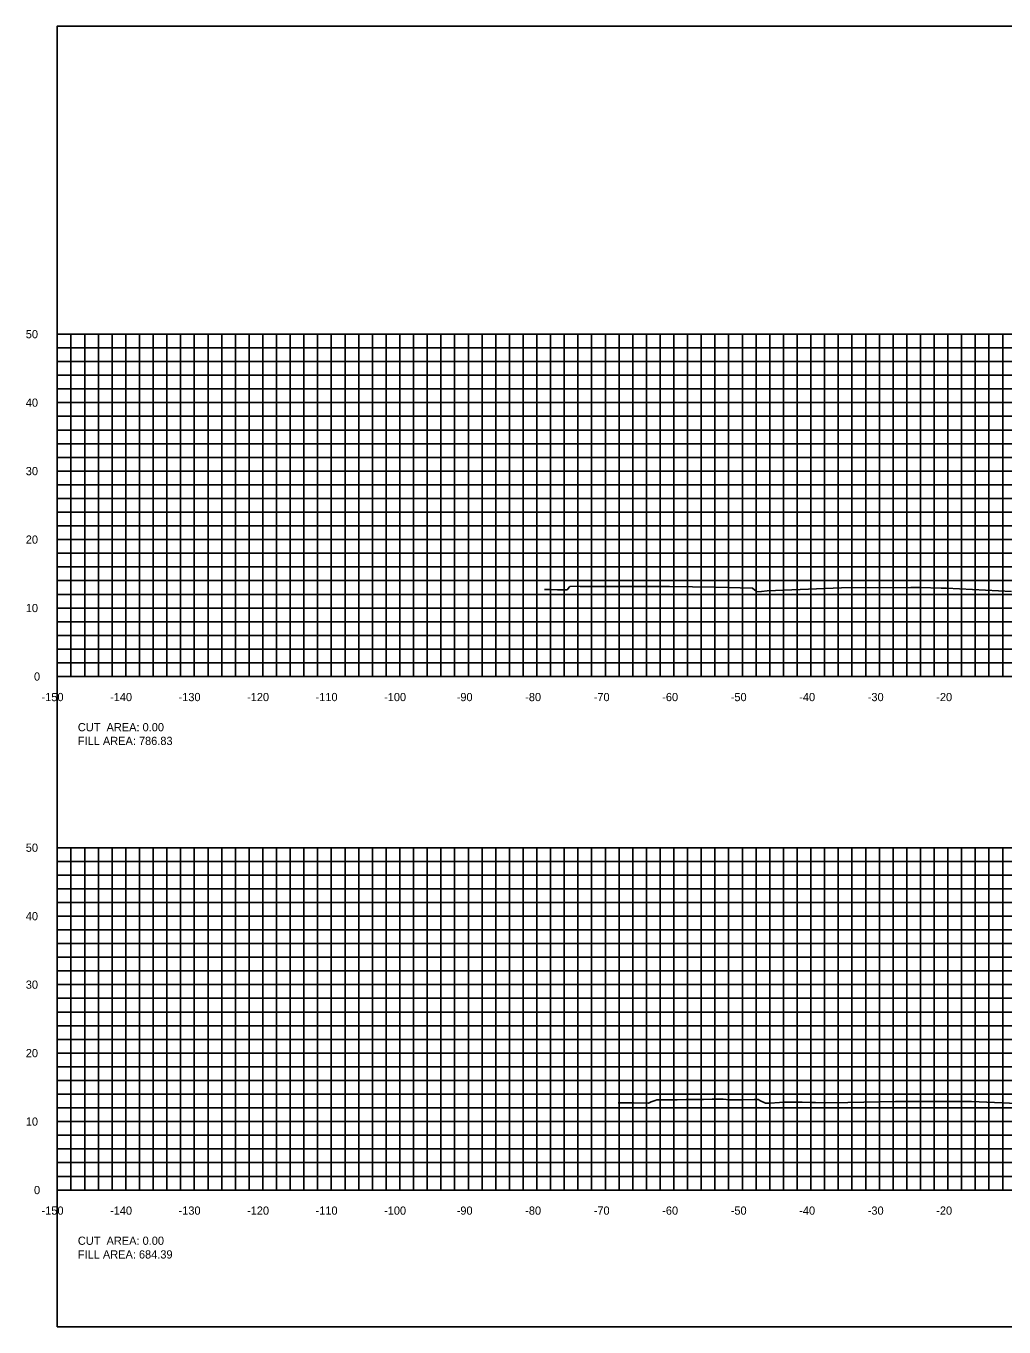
# Model space of a CAD drawing. Extents: x 1797714 to 1804825, y 249015 to 250269.
# Drawn here: x 1803496.4 to 1803639.2, y 250079.4 to 250269.4 of the extents above; entities that cross this region are included whole.
import ezdxf

# ---------------------------------------------------------------- set-up
doc = ezdxf.new("R2010")
doc.units = 0
for name, color, linetype in [('10', 7, 'Continuous'), ('31', 7, 'Continuous'), ('60', 7, 'Continuous'), ('ANNO-TXT', 7, 'Continuous'), ('Level 62', 7, 'Continuous'), ('M-ROADS', 7, 'Continuous')]:
    doc.layers.add(name, color=color, linetype=linetype)

msp = doc.modelspace()

# ---------------------------------------------------------------- linework, layer by layer
msp.add_lwpolyline([(1803501, 250079.43), (1803801, 250079.43), (1803801, 250269.43), (1803501, 250269.43)], close=True)
at = {"layer": '60'}
for p, q in [((1803500.94, 250224.43), (1803501, 250224.43)), ((1803501, 250174.43), (1803501, 250224.43)), ((1803500.94, 250214.43), (1803501, 250214.43)), ((1803500.94, 250204.43), (1803501, 250204.43)), ((1803500.94, 250194.43), (1803501, 250194.43)), ((1803500.94, 250184.43), (1803501, 250184.43)), ((1803500.94, 250174.43), (1803501, 250174.43)), ((1803501, 250174.43), (1803801, 250174.43)), ((1803501, 250174.37), (1803501, 250174.43)), ((1803511, 250174.37), (1803511, 250174.43)), ((1803521, 250174.37), (1803521, 250174.43)), ((1803531, 250174.37), (1803531, 250174.43)), ((1803541, 250174.37), (1803541, 250174.43)), ((1803551, 250174.37), (1803551, 250174.43)), ((1803561, 250174.37), (1803561, 250174.43)), ((1803571, 250174.37), (1803571, 250174.43)), ((1803581, 250174.37), (1803581, 250174.43)), ((1803591, 250174.37), (1803591, 250174.43)), ((1803601, 250174.37), (1803601, 250174.43)), ((1803611, 250174.37), (1803611, 250174.43)), ((1803621, 250174.37), (1803621, 250174.43)), ((1803631, 250174.37), (1803631, 250174.43)), ((1803500.94, 250149.43), (1803501, 250149.43)), ((1803501, 250099.43), (1803501, 250149.43)), ((1803500.94, 250139.43), (1803501, 250139.43)), ((1803500.94, 250129.43), (1803501, 250129.43)), ((1803500.94, 250119.43), (1803501, 250119.43)), ((1803500.94, 250109.43), (1803501, 250109.43)), ((1803500.94, 250099.43), (1803501, 250099.43)), ((1803501, 250099.43), (1803801, 250099.43)), ((1803501, 250099.37), (1803501, 250099.43)), ((1803511, 250099.37), (1803511, 250099.43)), ((1803521, 250099.37), (1803521, 250099.43)), ((1803531, 250099.37), (1803531, 250099.43)), ((1803541, 250099.37), (1803541, 250099.43)), ((1803551, 250099.37), (1803551, 250099.43)), ((1803561, 250099.37), (1803561, 250099.43)), ((1803571, 250099.37), (1803571, 250099.43)), ((1803581, 250099.37), (1803581, 250099.43)), ((1803591, 250099.37), (1803591, 250099.43)), ((1803601, 250099.37), (1803601, 250099.43)), ((1803611, 250099.37), (1803611, 250099.43)), ((1803621, 250099.37), (1803621, 250099.43)), ((1803631, 250099.37), (1803631, 250099.43))]:
    msp.add_line(p, q, dxfattribs=at)
at = {"layer": 'Level 62'}
for p, q in [((1803501, 250224.43), (1803801, 250224.43)), ((1803501, 250174.43), (1803501, 250224.43)), ((1803503, 250174.43), (1803503, 250224.43)), ((1803505, 250174.43), (1803505, 250224.43)), ((1803507, 250174.43), (1803507, 250224.43)), ((1803509, 250174.43), (1803509, 250224.43)), ((1803511, 250174.43), (1803511, 250224.43)), ((1803513, 250174.43), (1803513, 250224.43)), ((1803515, 250174.43), (1803515, 250224.43)), ((1803517, 250174.43), (1803517, 250224.43)), ((1803519, 250174.43), (1803519, 250224.43)), ((1803521, 250174.43), (1803521, 250224.43)), ((1803523, 250174.43), (1803523, 250224.43)), ((1803525, 250174.43), (1803525, 250224.43)), ((1803527, 250174.43), (1803527, 250224.43)), ((1803529, 250174.43), (1803529, 250224.43)), ((1803531, 250174.43), (1803531, 250224.43)), ((1803533, 250174.43), (1803533, 250224.43)), ((1803535, 250174.43), (1803535, 250224.43)), ((1803537, 250174.43), (1803537, 250224.43)), ((1803539, 250174.43), (1803539, 250224.43)), ((1803541, 250174.43), (1803541, 250224.43)), ((1803543, 250174.43), (1803543, 250224.43)), ((1803545, 250174.43), (1803545, 250224.43)), ((1803547, 250174.43), (1803547, 250224.43)), ((1803549, 250174.43), (1803549, 250224.43)), ((1803551, 250174.43), (1803551, 250224.43)), ((1803553, 250174.43), (1803553, 250224.43)), ((1803555, 250174.43), (1803555, 250224.43)), ((1803557, 250174.43), (1803557, 250224.43)), ((1803559, 250174.43), (1803559, 250224.43)), ((1803561, 250174.43), (1803561, 250224.43)), ((1803563, 250174.43), (1803563, 250224.43)), ((1803565, 250174.43), (1803565, 250224.43)), ((1803567, 250174.43), (1803567, 250224.43)), ((1803569, 250174.43), (1803569, 250224.43)), ((1803571, 250174.43), (1803571, 250224.43)), ((1803573, 250174.43), (1803573, 250224.43)), ((1803575, 250174.43), (1803575, 250224.43)), ((1803577, 250174.43), (1803577, 250224.43)), ((1803579, 250174.43), (1803579, 250224.43)), ((1803581, 250174.43), (1803581, 250224.43)), ((1803583, 250174.43), (1803583, 250224.43)), ((1803585, 250174.43), (1803585, 250224.43)), ((1803587, 250174.43), (1803587, 250224.43)), ((1803589, 250174.43), (1803589, 250224.43)), ((1803591, 250174.43), (1803591, 250224.43)), ((1803593, 250174.43), (1803593, 250224.43)), ((1803595, 250174.43), (1803595, 250224.43)), ((1803597, 250174.43), (1803597, 250224.43)), ((1803599, 250174.43), (1803599, 250224.43)), ((1803601, 250174.43), (1803601, 250224.43)), ((1803603, 250174.43), (1803603, 250224.43)), ((1803605, 250174.43), (1803605, 250224.43)), ((1803607, 250174.43), (1803607, 250224.43)), ((1803609, 250174.43), (1803609, 250224.43)), ((1803611, 250174.43), (1803611, 250224.43)), ((1803613, 250174.43), (1803613, 250224.43)), ((1803615, 250174.43), (1803615, 250224.43)), ((1803617, 250174.43), (1803617, 250224.43)), ((1803619, 250174.43), (1803619, 250224.43)), ((1803621, 250174.43), (1803621, 250224.43)), ((1803623, 250174.43), (1803623, 250224.43)), ((1803625, 250174.43), (1803625, 250224.43)), ((1803627, 250174.43), (1803627, 250224.43)), ((1803629, 250174.43), (1803629, 250224.43)), ((1803631, 250174.43), (1803631, 250224.43)), ((1803633, 250174.43), (1803633, 250224.43)), ((1803635, 250174.43), (1803635, 250224.43)), ((1803637, 250174.43), (1803637, 250224.43)), ((1803639, 250174.43), (1803639, 250224.43)), ((1803501, 250222.43), (1803801, 250222.43)), ((1803501, 250220.43), (1803801, 250220.43)), ((1803501, 250218.43), (1803801, 250218.43)), ((1803501, 250216.43), (1803801, 250216.43)), ((1803501, 250214.43), (1803801, 250214.43)), ((1803501, 250212.43), (1803801, 250212.43)), ((1803501, 250210.43), (1803801, 250210.43)), ((1803501, 250208.43), (1803801, 250208.43)), ((1803501, 250206.43), (1803801, 250206.43)), ((1803501, 250204.43), (1803801, 250204.43)), ((1803501, 250202.43), (1803801, 250202.43)), ((1803501, 250200.43), (1803801, 250200.43)), ((1803501, 250198.43), (1803801, 250198.43)), ((1803501, 250196.43), (1803801, 250196.43)), ((1803501, 250194.43), (1803801, 250194.43)), ((1803501, 250192.43), (1803801, 250192.43)), ((1803501, 250190.43), (1803801, 250190.43)), ((1803501, 250188.43), (1803801, 250188.43)), ((1803501, 250186.43), (1803801, 250186.43)), ((1803501, 250184.43), (1803801, 250184.43)), ((1803501, 250182.43), (1803801, 250182.43)), ((1803501, 250180.43), (1803801, 250180.43)), ((1803501, 250178.43), (1803801, 250178.43)), ((1803501, 250176.43), (1803801, 250176.43)), ((1803501, 250174.43), (1803801, 250174.43)), ((1803501, 250149.43), (1803801, 250149.43)), ((1803501, 250099.43), (1803501, 250149.43)), ((1803503, 250099.43), (1803503, 250149.43)), ((1803505, 250099.43), (1803505, 250149.43)), ((1803507, 250099.43), (1803507, 250149.43)), ((1803509, 250099.43), (1803509, 250149.43)), ((1803511, 250099.43), (1803511, 250149.43)), ((1803513, 250099.43), (1803513, 250149.43)), ((1803515, 250099.43), (1803515, 250149.43)), ((1803517, 250099.43), (1803517, 250149.43)), ((1803519, 250099.43), (1803519, 250149.43)), ((1803521, 250099.43), (1803521, 250149.43)), ((1803523, 250099.43), (1803523, 250149.43)), ((1803525, 250099.43), (1803525, 250149.43)), ((1803527, 250099.43), (1803527, 250149.43)), ((1803529, 250099.43), (1803529, 250149.43)), ((1803531, 250099.43), (1803531, 250149.43)), ((1803533, 250099.43), (1803533, 250149.43)), ((1803535, 250099.43), (1803535, 250149.43)), ((1803537, 250099.43), (1803537, 250149.43)), ((1803539, 250099.43), (1803539, 250149.43)), ((1803541, 250099.43), (1803541, 250149.43)), ((1803543, 250099.43), (1803543, 250149.43)), ((1803545, 250099.43), (1803545, 250149.43)), ((1803547, 250099.43), (1803547, 250149.43)), ((1803549, 250099.43), (1803549, 250149.43)), ((1803551, 250099.43), (1803551, 250149.43)), ((1803553, 250099.43), (1803553, 250149.43)), ((1803555, 250099.43), (1803555, 250149.43)), ((1803557, 250099.43), (1803557, 250149.43)), ((1803559, 250099.43), (1803559, 250149.43)), ((1803561, 250099.43), (1803561, 250149.43)), ((1803563, 250099.43), (1803563, 250149.43)), ((1803565, 250099.43), (1803565, 250149.43)), ((1803567, 250099.43), (1803567, 250149.43)), ((1803569, 250099.43), (1803569, 250149.43)), ((1803571, 250099.43), (1803571, 250149.43)), ((1803573, 250099.43), (1803573, 250149.43)), ((1803575, 250099.43), (1803575, 250149.43)), ((1803577, 250099.43), (1803577, 250149.43)), ((1803579, 250099.43), (1803579, 250149.43)), ((1803581, 250099.43), (1803581, 250149.43)), ((1803583, 250099.43), (1803583, 250149.43)), ((1803585, 250099.43), (1803585, 250149.43)), ((1803587, 250099.43), (1803587, 250149.43)), ((1803589, 250099.43), (1803589, 250149.43)), ((1803591, 250099.43), (1803591, 250149.43)), ((1803593, 250099.43), (1803593, 250149.43)), ((1803595, 250099.43), (1803595, 250149.43)), ((1803597, 250099.43), (1803597, 250149.43)), ((1803599, 250099.43), (1803599, 250149.43)), ((1803601, 250099.43), (1803601, 250149.43)), ((1803603, 250099.43), (1803603, 250149.43)), ((1803605, 250099.43), (1803605, 250149.43)), ((1803607, 250099.43), (1803607, 250149.43)), ((1803609, 250099.43), (1803609, 250149.43)), ((1803611, 250099.43), (1803611, 250149.43)), ((1803613, 250099.43), (1803613, 250149.43)), ((1803615, 250099.43), (1803615, 250149.43)), ((1803617, 250099.43), (1803617, 250149.43)), ((1803619, 250099.43), (1803619, 250149.43)), ((1803621, 250099.43), (1803621, 250149.43)), ((1803623, 250099.43), (1803623, 250149.43)), ((1803625, 250099.43), (1803625, 250149.43)), ((1803627, 250099.43), (1803627, 250149.43)), ((1803629, 250099.43), (1803629, 250149.43)), ((1803631, 250099.43), (1803631, 250149.43)), ((1803633, 250099.43), (1803633, 250149.43)), ((1803635, 250099.43), (1803635, 250149.43)), ((1803637, 250099.43), (1803637, 250149.43)), ((1803639, 250099.43), (1803639, 250149.43)), ((1803501, 250147.43), (1803801, 250147.43)), ((1803501, 250145.43), (1803801, 250145.43)), ((1803501, 250143.43), (1803801, 250143.43)), ((1803501, 250141.43), (1803801, 250141.43)), ((1803501, 250139.43), (1803801, 250139.43)), ((1803501, 250137.43), (1803801, 250137.43)), ((1803501, 250135.43), (1803801, 250135.43)), ((1803501, 250133.43), (1803801, 250133.43)), ((1803501, 250131.43), (1803801, 250131.43)), ((1803501, 250129.43), (1803801, 250129.43)), ((1803501, 250127.43), (1803801, 250127.43)), ((1803501, 250125.43), (1803801, 250125.43)), ((1803501, 250123.43), (1803801, 250123.43)), ((1803501, 250121.43), (1803801, 250121.43)), ((1803501, 250119.43), (1803801, 250119.43)), ((1803501, 250117.43), (1803801, 250117.43)), ((1803501, 250115.43), (1803801, 250115.43)), ((1803501, 250113.43), (1803801, 250113.43)), ((1803501, 250111.43), (1803801, 250111.43)), ((1803501, 250109.43), (1803801, 250109.43)), ((1803501, 250107.43), (1803801, 250107.43)), ((1803501, 250105.43), (1803801, 250105.43)), ((1803501, 250103.43), (1803801, 250103.43)), ((1803501, 250101.43), (1803801, 250101.43)), ((1803501, 250099.43), (1803801, 250099.43))]:
    msp.add_line(p, q, dxfattribs=at)
at = {"layer": 'M-ROADS'}
for points in [[(1803572.1, 250187.15), (1803572.86, 250187.13), (1803574, 250187.1), (1803574.17, 250187.09), (1803575.41, 250187.08), (1803575.78, 250187.54), (1803575.82, 250187.59), (1803577.04, 250187.61), (1803577.31, 250187.58), (1803590.38, 250187.56), (1803597.09, 250187.47), (1803602.49, 250187.31), (1803602.81, 250187.05), (1803603.05, 250186.81), (1803603.8, 250186.87), (1803604.64, 250186.92), (1803613.06, 250187.26), (1803615.47, 250187.36), (1803625.61, 250187.43), (1803626.96, 250187.44), (1803630.01, 250187.33), (1803630.15, 250187.32), (1803630.81, 250187.31), (1803640.28, 250186.86)], [(1803582.87, 250112.17), (1803582.96, 250112.18), (1803583.12, 250112.19), (1803583.61, 250112.19), (1803584.35, 250112.19), (1803584.84, 250112.19), (1803585.03, 250112.19), (1803585.14, 250112.18), (1803587.28, 250112.1), (1803587.41, 250112.16), (1803587.68, 250112.29), (1803588.25, 250112.5), (1803588.52, 250112.6), (1803591.46, 250112.63), (1803592.81, 250112.64), (1803594.46, 250112.64), (1803595.34, 250112.67), (1803596.57, 250112.68), (1803597.19, 250112.69), (1803598.21, 250112.68), (1803599.11, 250112.62), (1803600.24, 250112.63), (1803601.03, 250112.63), (1803602.73, 250112.64), (1803603.31, 250112.64), (1803603.63, 250112.48), (1803604.4, 250112.1), (1803604.68, 250112.11), (1803605.03, 250112.13), (1803606.43, 250112.23), (1803607.07, 250112.28), (1803608.7, 250112.27), (1803609.75, 250112.26), (1803611.01, 250112.24), (1803611.66, 250112.22), (1803613.19, 250112.15), (1803616.38, 250112.22), (1803623.37, 250112.37), (1803627.4, 250112.34), (1803634.43, 250112.34), (1803643.37, 250111.95)]]:
    msp.add_lwpolyline(points, dxfattribs=at)

# ---------------------------------------------------------------- texts
at = {"layer": '10'}
for s, p in [('-150', (1803498.7, 250170.83)), ('-140', (1803508.7, 250170.83)), ('-130', (1803518.7, 250170.83)), ('-120', (1803528.7, 250170.83)), ('-110', (1803538.7, 250170.83)), ('-100', (1803548.7, 250170.83)), ('-90', (1803559.3, 250170.83)), ('-80', (1803569.3, 250170.83)), ('-70', (1803579.3, 250170.83)), ('-60', (1803589.3, 250170.83)), ('-50', (1803599.3, 250170.83)), ('-40', (1803609.3, 250170.83)), ('-30', (1803619.3, 250170.83)), ('-20', (1803629.3, 250170.83)), ('-150', (1803498.7, 250095.83)), ('-140', (1803508.7, 250095.83)), ('-130', (1803518.7, 250095.83)), ('-120', (1803528.7, 250095.83)), ('-110', (1803538.7, 250095.83)), ('-100', (1803548.7, 250095.83)), ('-90', (1803559.3, 250095.83)), ('-80', (1803569.3, 250095.83)), ('-70', (1803579.3, 250095.83)), ('-60', (1803589.3, 250095.83)), ('-50', (1803599.3, 250095.83)), ('-40', (1803609.3, 250095.83)), ('-30', (1803619.3, 250095.83)), ('-20', (1803629.3, 250095.83))]:
    msp.add_text(s, height=1.2, dxfattribs=at).set_placement(p)
at = {"layer": '31'}
for s, p in [('50', (1803496.4, 250223.83)), ('40', (1803496.4, 250213.83)), ('30', (1803496.4, 250203.83)), ('20', (1803496.4, 250193.83)), ('10', (1803496.4, 250183.83)), ('0', (1803497.6, 250173.83)), ('50', (1803496.4, 250148.83)), ('40', (1803496.4, 250138.83)), ('30', (1803496.4, 250128.83)), ('20', (1803496.4, 250118.83)), ('10', (1803496.4, 250108.83)), ('0', (1803497.6, 250098.83))]:
    msp.add_text(s, height=1.2, dxfattribs=at).set_placement(p)
at = {"layer": '60'}
for p in [(1803501, 250174.43), (1803501, 250099.43)]:
    msp.add_text('-', height=0.0001, dxfattribs=at).set_placement(p)
at = {"layer": 'ANNO-TXT'}
for s, p in [('CUT  AREA: 0.00', (1803504, 250166.43)), ('FILL AREA: 786.83', (1803504, 250164.43)), ('CUT  AREA: 0.00', (1803504, 250091.43)), ('FILL AREA: 684.39', (1803504, 250089.43))]:
    msp.add_text(s, height=1.2, dxfattribs=at).set_placement(p)

doc.saveas('drawing.dxf')
